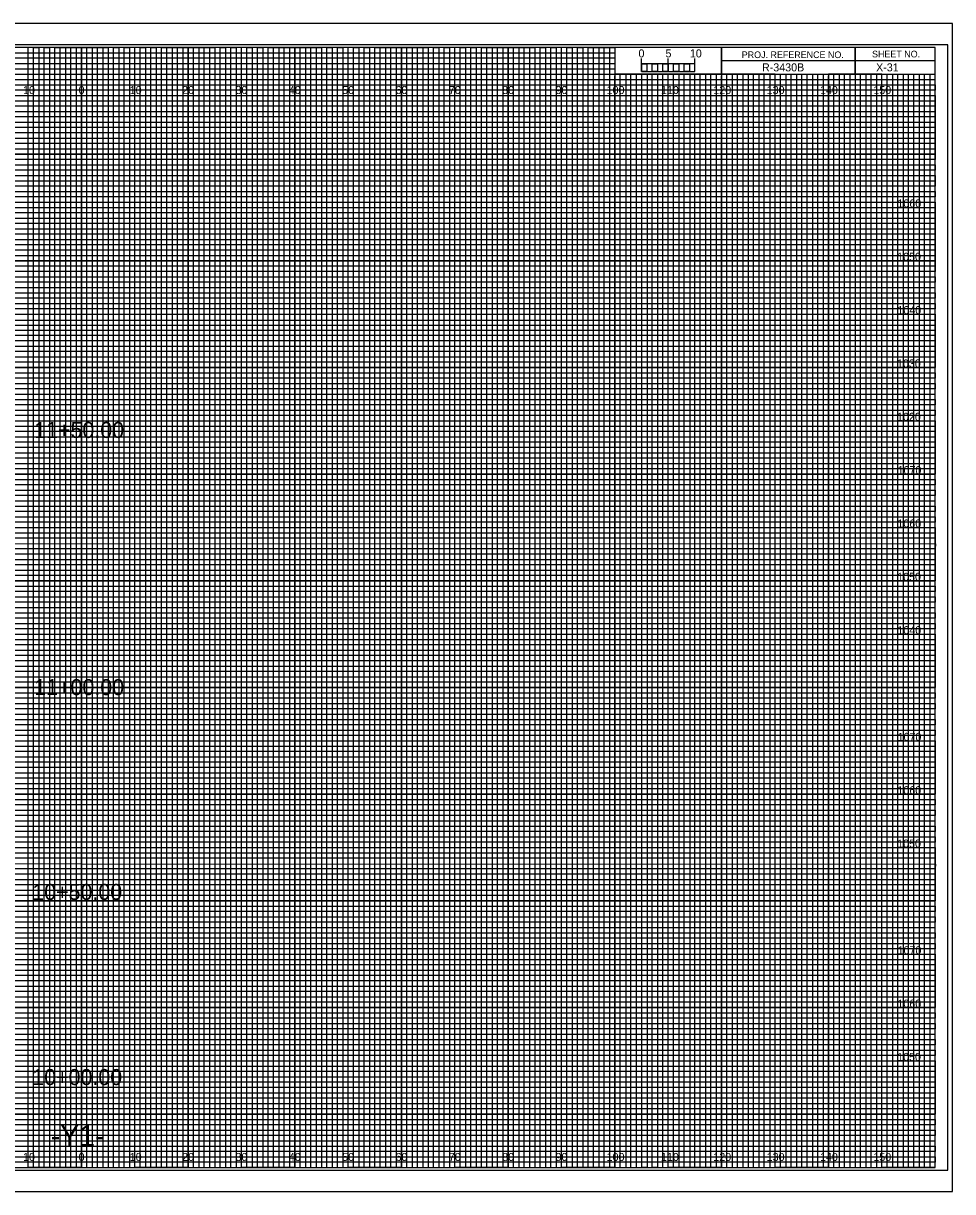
# Model space of a CAD drawing. Extents: x -13 to 323, y -5 to 215.
# Drawn here: x 149.1 to 323.3, y -4.5 to 214.5 of the extents above; entities that cross this region are included whole.
import ezdxf

# ---------------------------------------------------------------- set-up
doc = ezdxf.new("R2010")
doc.units = 0
for name, color, linetype in [('Exist Cross Section Cell', 7, 'Continuous'), ('Exist XS Center Line Elevation Label', 7, 'Continuous'), ('Exist XS Ground Line', 7, 'Continuous'), ('Prop CMT Conc Surface', 7, 'Continuous'), ('Prop CMT Concrete Structures', 7, 'Continuous'), ('Prop CMT Pvmt Course 1', 7, 'Continuous'), ('Prop CMT Pvmt Course 1 CG', 7, 'Continuous'), ('Prop CMT Pvmt Course 2', 7, 'Continuous'), ('Prop CMT Pvmt Course 3', 7, 'Continuous'), ('Prop CMT Pvmt Surface', 7, 'Continuous'), ('Prop CMT Slope Grass', 7, 'Continuous'), ('Prop CMT Subgrade Earthwork', 7, 'Continuous'), ('Prop XS Hydro Elevations', 7, 'Continuous'), ('Prop XS Roadway Elevations', 7, 'Continuous'), ('Prop XS SE Text', 7, 'Continuous'), ('Prop XS Side Slope Text', 7, 'Continuous'), ('Scratch_Level_0', 7, 'Continuous')]:
    doc.layers.add(name, color=color, linetype=linetype)

msp = doc.modelspace()

# ---------------------------------------------------------------- linework, layer by layer
at = {"layer": 'Exist XS Ground Line'}
for p, q in [((323.3, 214.5), (-13.4, 214.5)), ((-13.4, -4.5), (323.3, -4.5))]:
    msp.add_line(p, q, dxfattribs=at)
at = {"layer": 'Prop CMT Conc Surface'}
msp.add_lwpolyline([(-13.4, -4.5), (323.3, -4.5), (323.3, 214.5), (-13.4, 214.5)], close=True, dxfattribs=at)
at = {"layer": 'Prop CMT Concrete Structures'}
for p, q in [((0, 209), (260, 209)), ((260, 209), (260, 207.98)), ((260, 207.98), (0, 207.98)), ((0, 207), (260, 207)), ((260, 205.89), (0, 205.89)), ((260, 207), (260, 205.89)), ((0, 204), (320, 204))]:
    msp.add_line(p, q, dxfattribs=at)
for points in [[(0, 203), (270, 203), (320, 203), (320, 202), (0, 202)], [(0, 201), (320, 201), (320, 199), (0, 199)], [(0, 198), (320, 198), (320, 197), (0, 196.98)], [(0, 196), (320, 196), (320, 194), (0, 194)], [(0, 193), (320, 193), (320, 192), (0, 192)], [(0, 191), (320, 191), (320, 189), (0, 189)], [(0, 188), (320, 188), (320, 187), (0, 187)], [(0, 186), (320, 186), (320, 184), (0, 184)], [(0, 183), (320, 183), (320, 182), (0, 182)], [(0, 181), (320, 181), (320, 179), (0, 179)], [(0, 178), (320, 178), (320, 177), (0, 177)], [(0, 176), (320, 176), (320, 173.95), (320, 173), (320, 172), (0, 172)], [(0, 174), (320, 174), (320, 173), (0, 173)], [(0, 171), (320, 171), (320, 169), (0, 169.03)], [(0, 169.03), (320, 169), (320, 168), (0, 168)], [(0, 167), (320, 167), (320, 166), (0, 166)], [(0, 164), (320, 164), (320, 163), (0, 163)], [(0, 162), (320, 162), (320, 161), (0, 161)], [(-0.07, 158.89), (320, 158.89), (320, 157.88), (-0.07, 157.88)], [(0, 157), (320, 157), (320, 156), (0, 156)], [(0, 154), (320, 154), (320, 153), (0, 153)], [(0, 152), (320, 152), (320, 151), (0, 151)], [(0, 149), (320, 149), (320, 148), (0, 148)], [(0, 147), (320, 147), (320, 146), (0, 146)], [(0, 144), (320, 144), (320, 143), (0, 143)], [(0, 142), (320, 142), (320, 141), (0, 141)], [(0, 139), (320, 139), (319.99, 137.98), (0, 138)], [(0, 137), (320, 137), (320, 136), (0, 136)], [(0, 134), (320, 134), (320, 133), (0, 133)], [(0, 132), (320, 132), (320, 131), (0, 131)], [(0, 129), (320, 129), (320, 128), (0, 128)], [(0, 127), (320, 127), (320, 126), (0, 126)], [(0, 124), (320, 124), (320, 123), (0, 123)], [(0, 122), (320, 122), (320, 121), (0, 121)], [(0, 119), (320, 119), (320, 118), (0, 118)], [(0, 116.99), (320.07, 116.91), (320, 116), (0, 116)], [(0, 114), (320, 114), (320, 113), (0, 113)], [(0, 112), (320, 112), (320, 111), (0, 111)], [(0, 109), (320, 109), (320, 108), (0, 108)], [(0, 107), (320, 107), (320, 106), (0, 106)], [(0, 104), (320, 104), (320, 103), (0, 103)], [(0, 102), (320, 102), (320, 101), (0, 101)], [(0, 99), (320, 99), (320, 98), (0, 98)], [(0, 97), (320, 97), (320, 96), (0, 96)], [(0, 94), (320, 94), (320, 93), (0, 93)], [(0, 92), (320, 92), (320, 91), (0, 91)], [(0, 89), (320, 89), (320, 88), (0, 88)], [(0, 87), (320, 87), (320, 86), (0, 86)], [(0, 84), (320, 84), (320, 83), (0, 83)], [(0, 82), (320, 82), (320, 81), (0, 81)], [(0, 79), (320, 79), (319.99, 77.98), (0, 78)], [(0, 77), (320, 77), (320, 76), (0, 76)], [(0, 74), (320, 74), (320, 73), (0, 73)], [(0, 72), (320, 72), (320, 71), (0, 71)], [(0, 69), (320, 69), (320, 68), (0, 68)], [(0, 67), (320, 67), (320, 66), (0, 66)], [(0, 64), (320, 64), (320, 63), (0, 63)], [(0, 62), (320, 62), (320, 61), (0, 61)], [(0, 59), (320, 59), (320, 58), (0, 58)], [(0, 56.99), (320.07, 56.91), (320, 56), (0, 56)], [(0, 54), (320, 54), (320, 53), (0, 53)], [(0, 52), (320, 52), (320, 51), (0, 51)], [(0, 49), (320, 49), (320, 48), (0, 48)], [(0, 47), (320, 47), (320, 46), (0, 46)], [(0, 44), (320, 44), (320, 43), (0, 43)], [(0, 42), (320, 42), (320, 41), (0, 41)], [(0, 39), (320, 39), (320, 38), (0, 38)], [(0, 37), (320, 37), (320, 36), (0, 36)], [(0, 34), (320, 34), (320, 33), (0, 33)], [(0, 32), (320, 32), (320, 31), (0, 31)], [(0, 29), (320, 29), (320, 28), (0, 28)], [(0, 27), (320, 27), (320, 26), (0, 26)], [(0, 24), (320, 24), (320, 23), (0, 23)], [(0, 22), (320, 22), (320, 21), (0, 21)], [(0, 19), (320, 19), (320, 18), (0, 18)], [(0, 17), (320, 17), (320, 16), (0, 16)], [(0, 14), (320, 14), (320, 13), (0, 13)], [(0, 12), (320, 12), (320, 11), (0, 11)], [(0, 9), (320, 9), (320, 8), (0, 8)], [(0, 7), (320, 7), (320, 6), (0, 6)], [(0, 4), (320, 4), (320, 3), (0, 3)], [(0, 2), (320, 2), (320, 1), (0, 1)]]:
    msp.add_lwpolyline(points, dxfattribs=at)
at = {"layer": 'Prop CMT Pvmt Course 1'}
for p, q in [((265, 205.49), (265, 207.9)), ((265, 206.9), (265, 207.9)), ((270, 205.49), (270, 207.9)), ((275, 205.49), (275, 207.9)), ((275, 206.9), (275, 207.9))]:
    msp.add_line(p, q, dxfattribs=at)
for points in [[(275, 206.9), (265, 206.9), (265, 205.49), (275, 205.49)], [(265, 206.9), (266, 206.9), (266, 205.49), (265, 205.49)], [(267, 206.9), (268, 206.9), (268, 205.49), (267, 205.49)], [(269, 206.9), (270, 206.9), (270, 205.49), (269, 205.49)], [(271, 206.9), (272, 206.9), (272, 205.49), (271, 205.49)], [(273, 206.9), (274, 206.9), (274, 205.49), (273, 205.49)]]:
    msp.add_lwpolyline(points, close=True, dxfattribs=at)
at = {"layer": 'Prop CMT Pvmt Course 1 CG'}
for p, q in [((267, 205), (266.01, 205)), ((266.01, 205), (266.01, 0)), ((267, 0), (267, 205)), ((269, 205), (268, 205)), ((268, 205), (268, 0)), ((269, 0), (269, 205)), ((266.01, 0), (265, 0)), ((268, 0), (267, 0))]:
    msp.add_line(p, q, dxfattribs=at)
for points in [[(150, 0), (151, 0), (151, 210), (152, 210), (152, 0)], [(152, 0), (153, 0), (153, 210), (154, 210), (154, 0)], [(155, 0), (156, 0), (156, 210), (157, 210), (157, 0)], [(157, 0), (158, 0), (158, 210), (159, 210), (159, 0)], [(160, 0), (161, 0), (161, 210), (162, 210), (162, 0)], [(162, 0), (163, 0), (163, 210), (164, 210), (164, 0)], [(165, 0), (166, 0), (166, 210), (167, 210), (167, 0)], [(167, 0), (168, 0), (168, 210), (169, 210), (169, 0)], [(170, 0), (171, 0), (171, 210), (172, 210), (172, 0)], [(172, 0), (173, 0), (173, 210), (174, 210), (174, 0)], [(175, 0), (176, 0), (176, 210), (177, 210), (177, 0)], [(177, 0), (178, 0), (178, 210), (179, 210), (179, 0)], [(180, 0), (181, 0), (181, 210), (182, 210), (182, 0)], [(182, 0), (183, 0), (183, 210), (184, 210), (184, 0)], [(185, 0), (186, 0), (186, 210), (187, 210), (187, 0)], [(187, 0), (188, 0), (188, 210), (189, 210), (189, 0)], [(190, 0), (191, 0), (191, 210), (192, 210), (192, 0)], [(192, 0), (193, 0), (193, 210), (194, 210), (194, 0)], [(195, 0), (196, 0), (196, 210), (197, 210), (197, 0)], [(197, 0), (198, 0), (198, 210), (199, 210), (199, 0)], [(200, 0), (201, 0), (201, 210), (202, 210), (202, 0)], [(202, 0), (203, 0), (203, 210), (204, 210), (204, 0)], [(205, 0), (206, 0), (206, 210), (207, 210), (207, 0)], [(207, 0), (208, 0), (208, 210), (209, 210), (209, 0)], [(210, 0), (211, 0), (211, 210), (212, 210), (212, 0)], [(212, 0), (213, 0), (213, 210), (214, 210), (214, 0)], [(215, 0), (216, 0), (216, 210), (217, 210), (217, 0)], [(217, 0), (218, 0), (218, 210), (219, 210), (219, 0)], [(220, 0), (221, 0), (221, 210), (222, 210), (222, 0)], [(222, 0), (223, 0), (223, 210), (224, 210), (224, 0)], [(225, 0), (226, 0), (226, 210), (227, 210), (227, 0)], [(227, 0), (228, 0), (228, 210), (229, 210), (229, 0)], [(230, 0), (231, 0), (231, 210), (232, 210), (232, 0)], [(232, 0), (233, 0), (233, 210), (234, 210), (234, 0)], [(235, 0), (236, 0), (236, 210), (237, 210), (237, 0)], [(237, 0), (238, 0), (238, 210), (239, 210), (239, 0)], [(240, 0), (241, 0), (241, 210), (242, 210), (242, 0)], [(242, 0), (243, 0), (243, 210), (244, 210), (244, 0)], [(245, 0), (246, 0), (246, 210), (247, 210), (247, 0)], [(247, 0), (248, 0), (248, 210), (249, 210), (249, 0)], [(250, 0), (251, 0), (251, 210), (252, 210), (252, 0)], [(252, 0), (253, 0), (253, 210), (254, 210), (254, 0)], [(255, 0), (256, 0), (256, 210), (257, 210), (257, 0)], [(257, 0), (258, 0), (258, 210), (259, 210), (259, 0)], [(260, 0), (261, 0), (261, 205), (262.02, 205), (262.02, 0)], [(262, 0), (263, 0), (263, 205), (263.99, 205), (263.99, 0)], [(270, 0), (270.98, 0), (270.98, 205), (272, 205), (272, 0)], [(272, 0), (273, 0), (273, 205), (274.05, 205), (274.05, 0)], [(275, 0), (276, 0), (276, 205), (277, 205), (277, 0)], [(277, 0), (278, 0), (278, 205), (279, 205), (279, 0)], [(280, 0), (281, 0), (281, 205), (282, 205), (282, 0)], [(282, 0), (283, 0), (283, 205), (284, 205), (284, 0)], [(285, 0), (286, 0), (286, 205), (287, 205), (287, 0)], [(287, 0), (288, 0), (288, 205), (289, 205), (289, 0)], [(290, 0), (291, 0), (291, 205), (292, 205), (292, 0)], [(292, 0), (293, 0), (293, 205), (294, 205), (294, 0)], [(295, 0), (296, 0), (296, 205), (297, 205), (297, 0)], [(297, 0), (298, 0), (298, 205), (299, 205), (299, 0)], [(300, 0), (301, 0), (301, 205), (302, 205), (302, 0)], [(302, 0), (303, 0), (303, 205), (304, 205), (304, 0)], [(305, 0), (306, 0), (306, 205), (307, 205), (307, 0)], [(307, 0), (308, 0), (308, 205), (309, 205), (309, 0)], [(310, 0), (311, 0), (311, 205), (312, 205), (312, 0)], [(312, 0), (313, 0), (313, 205), (314, 205), (314, 0)], [(315, 0), (316, 0), (316, 205), (317, 205), (317, 0)], [(317, 0), (318, 0), (318, 205), (319, 205), (319, 0)]]:
    msp.add_lwpolyline(points, dxfattribs=at)
at = {"layer": 'Prop CMT Pvmt Course 2'}
for points in [[(145, 0), (155, 0), (155, 210), (165, 210), (165, 0), (175, 0), (175, 210), (185, 210), (185, 0), (195, 0), (195, 210), (205, 210), (205, 0), (215, 0), (215, 210), (225, 210), (225, 0), (235, 0), (235, 210), (245, 210), (245, 0), (255, 0), (255, 210), (259.93, 210), (260, 210), (260, 205), (264.99, 205), (264.99, 0), (275, 0), (275, 205), (285, 205), (285, 0), (295, 0), (295, 205), (305, 205), (305, 0), (315, 0), (315, 205)], [(0, 205), (275, 205)], [(0, 185), (320, 185), (320, 195), (0, 195)], [(0, 165), (320, 165), (320, 175), (0, 175)], [(0, 145), (320, 145), (320, 155), (0, 155)], [(0, 125), (320, 125), (320, 135), (0, 135)], [(0, 105), (320, 105), (320, 115), (0, 115)], [(0, 85), (320, 85), (320, 95), (0, 95)], [(0, 65), (320, 65), (320, 75), (0, 75)], [(0, 45), (320, 45), (320, 55), (0, 55)], [(0, 25), (320, 25), (320, 35), (0, 35)], [(0, 5), (320, 5), (320, 15), (0, 15)]]:
    msp.add_lwpolyline(points, dxfattribs=at)
at = {"layer": 'Prop CMT Pvmt Surface'}
for p, q in [((305, 210), (305, 205)), ((305, 205), (305, 210)), ((280, 207.5), (280, 205)), ((320, 207.49), (280, 207.49)), ((280, 205), (320, 205))]:
    msp.add_line(p, q, dxfattribs=at)
for points in [[(320, 210), (0, 210), (0, 0), (320, 0)], [(280, 210), (260, 210), (260, 205.03), (280, 205.03)], [(320, 210), (280, 210), (280, 205), (320, 205)]]:
    msp.add_lwpolyline(points, close=True, dxfattribs=at)
at = {"layer": 'Prop CMT Slope Grass'}
for p, q in [((150, 0), (150, 210)), ((160, 0), (160, 210)), ((170, 0), (170, 210)), ((180, 0), (180, 210)), ((190, 0), (190, 210)), ((200, 0), (200, 210)), ((210, 0), (210, 210)), ((220, 0), (220, 210)), ((230, 0), (230, 210)), ((240, 0), (240, 210)), ((250, 0), (250, 210)), ((260, 0), (260, 204.69)), ((270, 0), (270, 204.69)), ((280, 0), (280, 204.69)), ((290, 0), (290, 204.69)), ((300, 0), (300, 204.69)), ((310, 0), (310, 204.69)), ((0, 200), (320, 200)), ((0, 190), (320, 190)), ((0, 180), (320, 180)), ((0, 170), (320, 170)), ((0, 160), (320, 160)), ((0, 150), (320, 150)), ((0, 140), (320, 140)), ((0, 130), (320, 130)), ((0, 120), (320, 120)), ((0, 110), (320, 110)), ((0, 100), (320, 100)), ((0, 90), (320, 90)), ((0, 80), (320, 80)), ((0, 70), (320, 70)), ((0, 60), (320, 60)), ((0, 50), (320, 50)), ((0, 40), (320, 40)), ((0, 30), (320, 30)), ((0, 20), (320, 20)), ((0, 10), (320, 10))]:
    msp.add_line(p, q, dxfattribs=at)
at = {"layer": 'Prop CMT Subgrade Earthwork'}
msp.add_lwpolyline([(-10.8, -0.5), (322.4, -0.5), (322.4, 210.5), (-10.8, 210.5)], close=True, dxfattribs=at)
at = {"layer": 'Scratch_Level_0'}
for p, q in [((150, 210), (140, 210)), ((150, 0), (150, 210)), ((170, 210), (160, 210)), ((160, 210), (160, 0)), ((170, 0), (170, 210)), ((190, 210), (180, 210)), ((180, 210), (180, 0)), ((190, 0), (190, 210)), ((210, 210), (200, 210)), ((200, 210), (200, 0)), ((210, 0), (210, 210)), ((230, 210), (220, 210)), ((220, 210), (220, 0)), ((230, 0), (230, 210)), ((250, 210), (240, 210)), ((240, 210), (240, 0)), ((250, 0), (250, 210)), ((260, 210), (260, 0)), ((270, 0), (270, 205)), ((290, 205), (280, 205)), ((280, 205), (280, 0)), ((290, 0), (290, 205)), ((310, 205), (300, 205)), ((300, 205), (300, 0)), ((310, 0), (310, 205)), ((160, 0), (150, 0)), ((180, 0), (170, 0)), ((200, 0), (190, 0)), ((220, 0), (210, 0)), ((240, 0), (230, 0)), ((260, 0), (250, 0)), ((280, 0), (270, 0)), ((300, 0), (290, 0)), ((320, 0), (310, 0)), ((320, 0), (320, 0))]:
    msp.add_line(p, q, dxfattribs=at)
for points in [[(0, 200), (320, 200), (320, 190), (0, 190)], [(0, 180), (320, 180), (320, 170), (0, 170)], [(0, 160), (320, 160), (320, 150), (0, 150)], [(0, 140), (320, 140), (320, 130), (0, 130)], [(0, 120), (320, 120), (320, 110), (0, 110)], [(0, 100), (320, 100), (320, 90), (0, 90)], [(0, 80), (320, 80), (320, 70), (0, 70)], [(0, 60), (320, 60), (320, 50), (0, 50)], [(0, 40), (320, 40), (320, 30), (0, 30)], [(0, 20), (320, 20), (320, 10), (0, 10)]]:
    msp.add_lwpolyline(points, dxfattribs=at)

# ---------------------------------------------------------------- texts
at = {"layer": 'Exist Cross Section Cell'}
for s, p in [('10', (149.04, 201.25)), ('0', (159.45, 201.25)), ('0', (159.45, 201.25)), ('10', (169.04, 201.25)), ('20', (178.86, 201.25)), ('30', (188.86, 201.25)), ('40', (198.86, 201.25)), ('50', (208.86, 201.25)), ('60', (218.86, 201.25)), ('70', (228.86, 201.25)), ('80', (238.86, 201.25)), ('90', (248.86, 201.25)), ('100', (258.44, 201.25)), ('110', (268.62, 201.25)), ('120', (278.44, 201.25)), ('130', (288.44, 201.25)), ('140', (298.44, 201.25)), ('150', (308.44, 201.25)), ('10', (149.04, 1.25)), ('0', (159.45, 1.25)), ('0', (159.45, 1.25)), ('10', (169.04, 1.25)), ('20', (178.86, 1.25)), ('30', (188.86, 1.25)), ('40', (198.86, 1.25)), ('50', (208.86, 1.25)), ('60', (218.86, 1.25)), ('70', (228.86, 1.25)), ('80', (238.86, 1.25)), ('90', (248.86, 1.25)), ('100', (258.44, 1.25)), ('110', (268.62, 1.25)), ('120', (278.44, 1.25)), ('130', (288.44, 1.25)), ('140', (298.44, 1.25)), ('150', (308.44, 1.25))]:
    msp.add_text(s, height=1.5, dxfattribs=at).set_placement(p)
at = {"layer": 'Exist XS Center Line Elevation Label'}
for s, p in [('1060', (312.95, 180)), ('1050', (312.9, 170)), ('1040', (312.95, 160)), ('1030', (312.86, 150)), ('1020', (312.87, 140)), ('1070', (312.98, 130)), ('1060', (312.95, 120)), ('1050', (312.9, 110)), ('1040', (312.95, 100)), ('1070', (312.98, 80)), ('1060', (312.95, 70)), ('1050', (312.9, 60)), ('1070', (312.98, 40)), ('1060', (312.95, 30)), ('1050', (312.9, 20))]:
    msp.add_text(s, height=1.5, dxfattribs=at).set_placement(p)
at = {"layer": 'Prop CMT Pvmt Course 1'}
msp.add_text('0', height=1.5, dxfattribs=at).set_placement((264.41, 208.12))
at = {"layer": 'Prop CMT Pvmt Course 3'}
for s, p in [('5', (269.47, 208.12)), ('10', (274.04, 208.12))]:
    msp.add_text(s, height=1.5, dxfattribs=at).set_placement(p)
at = {"layer": 'Prop CMT Pvmt Surface'}
for s, p in [('PROJ. REFERENCE NO.', (283.77, 207.99)), ('SHEET NO.', (308.19, 208.12))]:
    msp.add_text(s, height=1.25, dxfattribs=at).set_placement(p)
at = {"layer": 'Prop XS Hydro Elevations'}
msp.add_text('R-3430B', height=1.5, dxfattribs=at).set_placement((287.56, 205.5))
at = {"layer": 'Prop XS Roadway Elevations'}
msp.add_text('-Y1-', height=4, dxfattribs=at).set_placement((154.21, 4))
at = {"layer": 'Prop XS SE Text'}
for s, p in [('11+50.00', (151.13, 136.78)), ('11+00.00', (151.13, 88.57)), ('10+50.00', (150.77, 50.18)), ('10+00.00', (150.77, 15.48))]:
    msp.add_text(s, height=3, dxfattribs=at).set_placement(p)
at = {"layer": 'Prop XS Side Slope Text'}
msp.add_text('X-31', height=1.5, dxfattribs=at).set_placement((308.95, 205.5))

doc.saveas('drawing.dxf')
